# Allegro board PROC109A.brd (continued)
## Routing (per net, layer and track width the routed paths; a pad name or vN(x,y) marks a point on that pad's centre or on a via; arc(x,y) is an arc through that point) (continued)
PRG1_CPSW_RGMII1_TD0: length 31.3
  TOP w0.135: v1(132.51,-42.34) 133.2,-42.34 135.25,-44.39 U19.28
  L03_SIG1 w0.121: v1(111.87,-42.26) 112.31,-42.26 112.6,-42.55 126.18,-42.55 126.3,-42.67 126.3,-42.93 126.42,-43.05 126.66,-43.05 126.78,-42.93 126.78,-42.67 126.9,-42.55 127.15,-42.55 127.27,-42.67 127.27,-42.93 127.39,-43.05 127.63,-43.05 127.75,-42.93 127.75,-42.67 127.87,-42.55 128.11,-42.55 128.23,-42.67 128.23,-42.93 128.35,-43.05 128.59,-43.05 128.71,-42.93 128.71,-42.67 128.83,-42.55 130.41,-42.55 131.34,-43.48 132.01,-43.48 132.51,-42.98 v1(132.51,-42.34)
  BOTTOM w0.135: U40.2 111.44,-41.84 v1(111.87,-42.26)
PRG1_CPSW_RGMII1_TD1: length 31.2
  TOP w0.135: U19.27 135.26,-43.89 134.16,-42.8 v1(134.16,-41.73)
  L03_SIG1 w0.121: v1(134.16,-41.73) 134.7,-41.73 134.86,-41.9 134.86,-42.07 134.44,-42.49 133.53,-42.49 132.29,-43.73 125.75,-43.73 125.47,-43.45 113.86,-43.45 113.26,-42.85 111.28,-42.85 v1(110.77,-42.34)
  BOTTOM w0.135: v1(110.77,-42.34) 110.77,-42.34 U40.3
PRG1_CPSW_RGMII1_TD2: length 31.2
  TOP w0.135: v1(134.92,-42.88) 135.44,-43.39 U19.26
  L03_SIG1 w0.121: v1(111.87,-43.29) 113.16,-43.29 113.7,-43.82 120.23,-43.82 120.75,-44.34 126.06,-44.34 126.18,-44.46 126.18,-44.81 126.3,-44.93 126.54,-44.93 126.66,-44.81 126.66,-44.39 126.78,-44.27 127.02,-44.27 127.14,-44.39 127.14,-44.81 127.26,-44.93 127.51,-44.93 127.63,-44.81 127.63,-44.39 127.75,-44.27 127.99,-44.27 128.11,-44.39 128.11,-44.81 128.23,-44.93 128.47,-44.93 128.59,-44.81 128.59,-44.46 128.71,-44.34 132.08,-44.34 133.55,-42.88 v1(134.92,-42.88)
  BOTTOM w0.135: U40.4 111.42,-42.84 v1(111.87,-43.29)
PRG1_CPSW_RGMII1_TD3: length 31.2
  TOP w0.135: U19.25 135.88,-42.89 135.69,-42.7 v1(135.69,-41.73)
  L03_SIG1 w0.121: v1(110.68,-43.34) 111.05,-43.71 112.37,-43.71 113.57,-44.91 120.3,-44.91 120.59,-45.2 131.84,-45.2 133.4,-43.64 135.33,-43.64 136,-42.97 136,-42.04 v1(135.69,-41.73)
  BOTTOM w0.135: U40.5 v1(110.68,-43.34)
PRG1_CPSW_RGMII1_TX_CTL: length 30.5
  TOP w0.135: U19.37 136.66,-49.14 136.58,-49.23 v1(136.12,-49.23)
  L03_SIG1 w0.121: v1(111.87,-44.2) 111.87,-44.96 112.85,-45.95 114.71,-45.95 115.32,-46.56 133.89,-46.56 136.12,-48.78 v1(136.12,-49.23)
  BOTTOM w0.135: v1(111.87,-44.2) 111.5,-43.84 U40.6
PRG1_CPSW_RGMII1_TXC: length 31.3
  TOP w0.135: U19.29 135.19,-44.89 133.35,-43.05 v1(131.76,-43.05)
  L03_SIG1 w0.121: v1(110.68,-44.34) 110.24,-43.9 110.24,-42.17 110.57,-41.84 121.05,-41.84 121.54,-41.35 127.71,-41.35 128.27,-41.91 130.61,-41.91 v1(131.76,-43.05)
  BOTTOM w0.135: U40.7 v1(110.68,-44.34)
PRG1_CPSW_RGMII2_CLK: length 19.5
  TOP w0.135: R50.2 130.58,-27.94 132.18,-26.34 132.18,-20.02 133.35,-18.85 138.28,-18.85 138.79,-19.36 R13.1
PRG1_CPSW_RGMII2_CLK_R: length 2.7
  TOP w0.135: R50.1 126.29,-27.94 126.03,-27.69 126.03,-27.38 125.79,-27.14 U6.5
PRG1_CPSW_RGMII2_GPIO_1: length 43.9
  TOP w0.135: U7.22 138.18,-21.62 v1(137.72,-21.16) 137.71,-21.17 R12.2
  L03_SIG1 w0.121: v1(162.18,-21.41) 162.18,-20.37 160.35,-18.54 139.83,-18.54 137.72,-20.65 v1(137.72,-21.16)
  BOTTOM w0.135: R12.2 137.71,-21.17 v1(137.72,-21.16) ; Q12.3 162.94,-30.47 162.18,-29.72 v1(162.18,-21.41)
PRG1_CPSW_RGMII2_RD0: length 73.8
  TOP w0.102: 87.62,-44.31 U18.AA10
  TOP w0.135: v1(133.99,-28.78) 133.83,-28.93 133.83,-29.38 R64.1 134.52,-29.51 134.7,-29.34 134.7,-28.65 135.5,-27.84 U7.33 ; v1(104.78,-39.5) 103.99,-39.5 103.33,-40.16 103.33,-41.07 102.74,-41.66 101.98,-41.66 98.73,-44.91 89,-44.91 88.41,-44.31 87.62,-44.31
  L03_SIG1 w0.121: v1(133.99,-28.78) 133.4,-29.36 132.72,-29.36 132.23,-28.88 131.62,-28.88 131.45,-28.71 131.45,-26.8 131.33,-26.68 130.99,-26.68 130.87,-26.8 130.87,-29 130.74,-29.12 130.44,-29.12 130.28,-28.96 130.28,-26.95 130.13,-26.8 129.79,-26.8 127.93,-28.66 121.96,-28.66 121.87,-28.75 121.31,-28.75 121.22,-28.66 120.86,-28.66 117.26,-32.25 117.26,-32.54 116.87,-32.94 116.58,-32.94 115.4,-34.11 115.4,-34.12 114.63,-34.89 114.63,-36.94 113.27,-38.3 102.74,-38.3 102.62,-38.42 102.62,-39.38 102.74,-39.5 v1(104.78,-39.5)
  BOTTOM w0.135: v1(133.99,-28.78) 133.99,-29.48 R64.1
PRG1_CPSW_RGMII2_RD1: length 73.6
  TOP w0.102: 87.74,-44.59 86.67,-44.59 U18.Y10
  TOP w0.135: 87.74,-44.59 88.28,-44.59 88.87,-45.18 98.96,-45.18 102.18,-41.96 102.82,-41.96 103.76,-41.02 v1(103.76,-40.51) ; v1(133.99,-30.24) 133.99,-30.25 133.78,-30.45 133.78,-30.75 R68.2 134.51,-30.94 135,-30.45 135,-28.98 135.64,-28.34 U7.34
  L03_SIG1 w0.121: v1(133.99,-30.24) 127.44,-30.24 127.1,-30.58 126.45,-30.58 126.13,-30.26 126.13,-29.29 126.01,-29.17 125.77,-29.17 125.65,-29.29 125.65,-30.26 125.53,-30.38 125.29,-30.38 125.17,-30.26 125.17,-29.29 125.05,-29.17 124.81,-29.17 124.69,-29.29 124.69,-30.98 124.57,-31.1 124.32,-31.1 124.2,-30.98 124.2,-29.29 124.08,-29.17 123.84,-29.17 123.72,-29.29 123.72,-30.26 123.6,-30.38 122.4,-30.38 119.38,-33.4 119.38,-34.82 118.44,-35.76 116.53,-35.76 113.48,-38.81 107.11,-38.81 104.14,-41.78 102.36,-41.78 102.23,-41.66 102.23,-41.17 102.36,-41.05 103.23,-41.05 v1(103.76,-40.51)
  BOTTOM w0.135: v1(133.99,-30.24) 133.99,-30.92 R68.2
PRG1_CPSW_RGMII2_RD2: length 73.7
  TOP w0.102: 87.33,-43.54 86.67,-43.54 U18.Y11
  TOP w0.135: v1(132.49,-32.08) 132.63,-32.23 R71.1 133.24,-32.23 133.82,-31.65 134.29,-31.65 135.28,-30.66 135.28,-29.16 135.6,-28.84 U7.35 ; 87.33,-43.54 87.37,-43.58 95.86,-43.58 97.93,-41.52 100.04,-41.52 v1(100.63,-42.11)
  L03_SIG1 w0.121: v1(100.63,-42.11) 101.57,-43.05 104.27,-43.05 104.52,-42.8 104.52,-41.78 107.24,-39.07 113.59,-39.07 116.64,-36.02 118.54,-36.02 119.63,-34.92 119.63,-33.51 121.6,-31.55 123.91,-31.55 124.59,-32.23 127.6,-32.23 127.72,-32.11 127.72,-30.65 127.84,-30.53 128.08,-30.53 128.2,-30.65 128.2,-32.14 128.32,-32.26 128.56,-32.26 128.68,-32.14 128.68,-30.65 128.8,-30.53 129.04,-30.53 129.16,-30.65 129.16,-32.14 129.28,-32.26 129.53,-32.26 129.65,-32.14 129.65,-30.65 129.77,-30.53 130.01,-30.53 130.13,-30.65 130.13,-32.14 130.25,-32.26 130.49,-32.26 130.61,-32.14 130.61,-30.65 130.73,-30.53 130.97,-30.53 131.09,-30.65 131.09,-31.86 131.32,-32.08 v1(132.49,-32.08)
  BOTTOM w0.135: v1(132.49,-32.08) 132.71,-32.3 R230.2
PRG1_CPSW_RGMII2_RD3: length 73.6
  TOP w0.102: v2(85.36,-43.77) 85.39,-43.74 U18.V12
  TOP w0.135: U7.36 135.74,-29.34 135.59,-29.5 135.59,-30.82 134.73,-31.68 R72.1 134.94,-32.44 135.28,-32.44 v1(135.48,-32.23)
  L03_SIG1 w0.102: v2(85.36,-43.77) 85.42,-43.71 86.19,-43.71 86.31,-43.59 87.6,-43.59
  L03_SIG1 w0.121: 87.6,-43.59 88.22,-42.98 98.15,-42.98 100.28,-45.11 101.8,-45.11 102.58,-44.34 105.52,-44.34 106.25,-43.61 106.25,-42.56 108.97,-39.83 117.87,-39.83 118.59,-39.11 118.59,-36.4 119.48,-35.51 119.99,-35.51 122.78,-32.72 126.35,-32.72 126.47,-32.84 126.47,-33.18 126.59,-33.3 126.83,-33.3 126.95,-33.18 126.95,-32.84 127.07,-32.72 127.32,-32.72 127.44,-32.84 127.44,-33.18 127.56,-33.3 127.8,-33.3 127.92,-33.18 127.92,-32.84 128.04,-32.72 128.28,-32.72 128.4,-32.84 128.4,-33.18 128.52,-33.3 128.76,-33.3 128.88,-33.18 128.88,-32.84 129.01,-32.72 129.25,-32.72 129.37,-32.84 129.37,-33.18 129.49,-33.3 129.73,-33.3 129.85,-33.18 129.85,-32.84 129.97,-32.72 133.06,-32.72 133.19,-32.59 133.19,-31.34 133.31,-31.22 133.53,-31.22 133.67,-31.36 133.67,-32.42 133.79,-32.54 134.03,-32.54 134.15,-32.42 134.15,-31.34 134.28,-31.22 134.52,-31.22 134.64,-31.34 134.64,-32.59 134.76,-32.71 135.01,-32.71 v1(135.48,-32.23)
  BOTTOM w0.135: R229.2 134.79,-32.23 v1(135.48,-32.23)
PRG1_CPSW_RGMII2_RSTN: length 5.1
  TOP w0.135: U7.43 140.18,-32.16 v1(139.06,-33.27)
  BOTTOM w0.135: U34.4 138.45,-33.39 138.57,-33.27 v1(139.06,-33.27)
PRG1_CPSW_RGMII2_RX_CTL: length 73.8
  TOP w0.102: 87.49,-43.32 U18.Y12
  TOP w0.135: 87.49,-43.32 95.62,-43.32 97.69,-41.25 99.97,-41.25 v1(100.2,-41.02) ; U7.38 137.68,-31.07 137.41,-31.35 136.56,-31.35 136.22,-31.69 R73.2 136.44,-32.44 136.73,-32.44 v1(136.93,-32.23)
  L03_SIG1 w0.121: v1(100.2,-41.02) 101.22,-40 105.33,-40 106.78,-38.56 113.38,-38.56 116.5,-35.43 118.4,-35.43 118.6,-35.24 118.6,-33.16 119.27,-32.5 119.73,-32.5 119.9,-32.33 119.9,-32.16 119.08,-31.34 119.08,-31.17 119.25,-30.99 119.42,-30.99 120.24,-31.81 120.43,-31.81 120.59,-31.66 120.59,-31.49 119.76,-30.65 119.76,-30.48 119.93,-30.31 120.1,-30.31 120.94,-31.16 121.14,-31.16 121.3,-31 121.3,-30.83 120.44,-29.97 120.44,-29.8 120.61,-29.63 120.78,-29.63 121.63,-30.48 121.85,-30.48 121.99,-30.33 121.99,-30.16 121.12,-29.29 121.12,-29.12 121.24,-29 121.98,-29 122.06,-28.91 126.7,-28.91 127.7,-29.91 132.9,-29.91 133.17,-29.64 134.34,-29.64 v1(136.93,-32.23)
  BOTTOM w0.135: v1(136.93,-32.23) 136.86,-32.3 R228.1
PRG1_CPSW_RGMII2_RXC: length 70.4
  TOP w0.102: U18.V10 84.98,-44.31 v2(84.93,-44.37)
  TOP w0.135: v1(132.18,-28.07) 132.95,-28.07 R51.1
  L03_SIG1 w0.121: v1(132.18,-28.07) 134.19,-28.07 136.35,-30.23 136.35,-30.89 137.54,-32.08 137.54,-33.31 136.34,-34.51 131.34,-34.51 130.84,-34.01 125.29,-34.01 123.74,-35.56 121.92,-35.56 120.98,-36.5 120.98,-38.13 118.76,-40.34 110.93,-40.34 104.56,-46.71 103.48,-46.71 102.85,-46.08 96.8,-46.08 95.63,-44.9 87.6,-44.9 87.35,-44.65 85.21,-44.65 v2(84.93,-44.37)
PRG1_CPSW_RGMII2_RXC_R: length 2.8
  TOP w0.135: R51.2 134.5,-28.05 135.21,-27.34 U7.32
PRG1_CPSW_RGMII2_TD0: length 75.4
  TOP w0.102: U18.Y6 87.39,-46.31 87.74,-46.66
  TOP w0.135: U7.28 135.06,-25.34 134.66,-24.95 v1(134.66,-24.51) ; v1(112.52,-37.34) 113,-37.34 113.79,-38.13 113.79,-38.9 113.66,-39.04 113.16,-39.04 113.03,-39.17 113.03,-39.44 113.16,-39.58 114.11,-39.58 114.25,-39.71 114.25,-39.98 114.11,-40.12 113.16,-40.12 113.03,-40.25 113.03,-40.52 113.16,-40.66 114.11,-40.66 114.25,-40.79 114.25,-44.78 113.06,-45.97 110.29,-45.97 109.52,-46.74 109.52,-47.42 108.98,-47.97 96.89,-47.97 96.24,-48.62 89.69,-48.62 87.74,-46.66
  L03_SIG1 w0.121: v1(112.52,-37.34) 112.52,-35.79 115.46,-32.85 115.46,-32.25 120.63,-27.09 120.63,-25.71 121.97,-24.36 128,-24.36 128.61,-23.75 133.9,-23.75 v1(134.66,-24.51)
PRG1_CPSW_RGMII2_TD1: length 75.4
  TOP w0.102: 87.74,-45.52 87.73,-45.51 87.09,-45.51 U18.AA8
  TOP w0.135: 87.74,-45.52 89.15,-46.94 96.16,-46.94 96.9,-46.2 100.74,-46.2 102.3,-44.64 102.84,-44.64 104.78,-42.7 104.78,-41.83 105.08,-41.53 107.11,-41.53 v1(111.3,-37.34) ; U7.27 135.56,-24.84 135.56,-24.84 v1(135.52,-24.84)
  L03_SIG1 w0.121: v1(135.52,-24.84) 136.42,-24.84 136.63,-25.04 136.63,-25.42 136.51,-25.54 134.53,-25.54 134.41,-25.66 134.41,-25.9 134.53,-26.02 135.24,-26.02 135.36,-26.14 135.36,-26.42 135.49,-26.54 135.73,-26.54 135.85,-26.42 135.85,-26.14 135.97,-26.02 136.51,-26.02 136.63,-26.14 136.63,-27.31 136.48,-27.46 133.63,-27.46 133.27,-27.09 133.27,-24.5 132.79,-24.03 128.88,-24.03 128.27,-24.64 122.17,-24.64 120.95,-25.86 120.95,-27.12 115.72,-32.35 115.72,-32.96 113.94,-34.73 113.94,-36.78 112.93,-37.79 111.76,-37.79 v1(111.3,-37.34)
PRG1_CPSW_RGMII2_TD2: length 75.4
  TOP w0.102: U18.Y9 87.31,-44.81
  TOP w0.135: v1(134.6,-23.18) 134.6,-23.63 135.32,-24.34 U7.26 ; v1(108.25,-37.34) 105.59,-40 105.28,-40 103.12,-42.16 103.12,-42.67 102.49,-43.31 101.22,-43.31 99.08,-45.45 88.66,-45.45 88.14,-44.93 87.43,-44.93 87.31,-44.81
  L03_SIG1 w0.121: v1(108.25,-37.34) 107.81,-37.34 107.77,-37.3 101.74,-37.3 101.52,-37.08 101.52,-36.74 101.73,-36.54 111.42,-36.54 115.21,-32.75 115.21,-32.14 120.37,-26.98 120.37,-25.6 121.87,-24.11 127.89,-24.11 128.51,-23.49 134.29,-23.49 v1(134.6,-23.18)
PRG1_CPSW_RGMII2_TD3: length 74.9
  TOP w0.102: U18.W9 85.89,-45.24 v2(85.93,-45.28)
  TOP w0.135: U7.25 135.74,-23.84 135.52,-23.62 v1(135.52,-23.18)
  L03_SIG1 w0.121: v2(85.93,-45.28) 87.04,-45.28 87.17,-45.42 95.05,-45.42 96.22,-46.59 102.62,-46.59 103.3,-47.27 106.54,-47.27 109.65,-44.16 109.65,-42.39 110.46,-41.58 119.93,-41.58 123.48,-38.04 123.48,-36.54 125.5,-34.52 130.56,-34.52 131.06,-35.02 136.56,-35.02 138.84,-32.74 138.84,-28.75 137.29,-27.2 137.29,-24.95 v1(135.52,-23.18)
PRG1_CPSW_RGMII2_TX_CTL: length 74.8
  TOP w0.102: v2(85.36,-45.28) 85.39,-45.24 U18.V9
  TOP w0.135: U7.37 137.18,-30.83 137.19,-30.84 v1(137.19,-30.89)
  L03_SIG1 w0.121: v1(137.19,-30.89) 137.19,-30.45 135.01,-28.28 135.01,-28.01 135.25,-27.76 137.48,-27.76 138.58,-28.86 138.58,-32.64 136.45,-34.77 131.16,-34.77 130.66,-34.27 125.39,-34.27 123.72,-35.94 123.1,-35.94 122.28,-36.76 122.28,-37.96 119.47,-40.77 113.42,-40.77 112.86,-41.33 110.36,-41.33 109.4,-42.29 109.4,-43.22 105.65,-46.96 103.37,-46.96 102.74,-46.34 96.47,-46.34 95.3,-45.16 87.43,-45.16 87.18,-44.92 85.73,-44.92 v2(85.36,-45.28)
PRG1_CPSW_RGMII2_TXC: length 8
  TOP w0.102: 87.74,-45.24 87.35,-45.24 87.15,-45.04 86.67,-45.04 U18.Y8
  TOP w0.135: 87.74,-45.24 88.01,-45.24 88.59,-45.82 93.25,-45.82 93.72,-46.29 R23.1
PRG1_CPSW_RGMII2_TXC_R: length 67.1
  TOP w0.135: R23.2 96.09,-46.33 96.62,-45.8 99.62,-45.8 101.6,-43.81 103.15,-43.81 104.47,-42.49 104.47,-41.71 105.13,-41.05 106.07,-41.05 v1(109.78,-37.34) ; U7.29 135.14,-25.84 134.09,-24.79 v1(132.61,-24.79)
  L03_SIG1 w0.121: v1(109.78,-37.34) 110.49,-38.05 113.08,-38.05 114.27,-36.86 114.27,-34.76 116.36,-32.68 116.76,-32.68 117.01,-32.43 117.01,-32.09 120.88,-28.22 123.46,-28.22 123.58,-28.1 123.58,-26.54 123.73,-26.39 123.92,-26.39 124.06,-26.54 124.06,-28.1 124.18,-28.22 124.4,-28.22 124.52,-28.1 124.52,-26.51 124.64,-26.39 124.88,-26.39 125,-26.51 125,-28.07 125.15,-28.22 125.36,-28.22 125.48,-28.1 125.48,-26.51 125.6,-26.39 125.85,-26.39 125.97,-26.51 125.97,-28.07 126.11,-28.22 126.33,-28.22 126.45,-28.1 126.45,-26.51 126.57,-26.39 126.84,-26.39 126.96,-26.51 126.96,-28.1 127.15,-28.3 127.56,-28.3 131.06,-24.79 v1(132.61,-24.79)
PRG1_CPSW_RGMII_INTN: length 94.1
  TOP w0.102: 87.74,-42.68 87.62,-42.68 87.62,-42.68 87.03,-42.68 U18.AA13
  TOP w0.135: v1(142.39,-51.28) 142.21,-51.46 141.85,-51.46 R136.2 141.66,-50.8 140.68,-49.82 U19.44 ; U7.44 140.68,-31.67 v1(140.69,-31.67) ; 87.74,-42.68 94.93,-42.68 94.94,-42.67 95,-42.67 97.04,-40.62 99.33,-40.62 99.63,-40.32 101.36,-40.32 101.98,-40.94 102.41,-40.94 102.67,-40.69 102.67,-39.79 103.69,-38.77 105.75,-38.77 107.97,-36.56 108.57,-36.56 108.79,-36.34 114.62,-36.34 115.7,-37.41 123.12,-37.41 v1(124.44,-38.73)
  L03_SIG1 w0.121: v1(140.69,-31.67) 140.69,-32.33 137.64,-35.38 131.04,-35.38 130.43,-34.78 125.62,-34.78 123.73,-36.67 123.73,-38.03 v1(124.44,-38.73)
  BOTTOM w0.135: v1(142.39,-51.28) 142.39,-50.83 141.66,-50.11 141.14,-50.11 136.69,-45.66 136.69,-42.21 136.69,-42.15 136.69,-36.18 137.85,-35.03 138.87,-35.03 139.5,-34.4 139.5,-33.33 140.69,-32.13 v1(140.69,-31.67)
PRG1_IEP0_EDC_LATCH_IN0: length 33
  TOP w0.102: U18.Y4 86.67,-47.59 87.14,-47.59 87.58,-48.03 87.58,-48.03 87.74,-48.19
  TOP w0.135: 87.74,-48.19 89.42,-49.88 89.46,-49.91 98.15,-49.91 v1(98.73,-50.5)
  BOTTOM w0.135: v1(98.73,-50.5) 98.78,-50.54 98.78,-55.39 98.91,-55.52 108.72,-55.52 J5.8
PRG1_IEP0_EDC_LATCH_IN1: length 53.4
  TOP w0.102: U18.V13 85.41,-42.82 v2(85.93,-42.3)
  L03_SIG1 w0.102: v2(85.93,-42.3) 86.65,-42.3 87.44,-41.5 87.74,-41.5
  L03_SIG1 w0.121: 87.74,-41.5 98.72,-41.5 100.65,-43.43 104.39,-43.43 105.35,-42.48 105.38,-42.48 105.63,-42.23 105.63,-42.2 108.51,-39.32 114.45,-39.32 v1(114.88,-38.89)
  BOTTOM w0.135: v1(114.88,-38.89) 114.88,-53.97 116.95,-56.04 J5.12
PRG1_IEP0_EDC_SYNC_OUT0: length 34.1
  TOP w0.102: v2(85.36,-47.86) 85.31,-47.81 U18.U3
  L03_SIG1 w0.121: v1(98.73,-49) 88.32,-49 87.71,-48.39 85.89,-48.39 v2(85.36,-47.86)
  BOTTOM w0.135: v1(98.73,-49) 98.73,-49.89 98.3,-50.32 98.3,-50.67 98.51,-50.88 98.51,-55.51 98.81,-55.8 108,-55.8 109.33,-57.13 J5.6
PRG1_IEP0_EDC_SYNC_OUT1: length 36.1
  TOP w0.102: 84.41,-49.66 84.41,-49.33 84.11,-49.04 84.11,-48.59 U18.T2
  TOP w0.135: 84.41,-49.66 84.41,-49.87 86.44,-51.89 86.44,-52.99 88.3,-54.85 98.62,-54.85 98.69,-54.91 v1(99.21,-54.91)
  BOTTOM w0.135: v1(99.21,-54.91) 110.65,-54.91 J5.10
PRG1_MDIO0_MDC: length 103.3
  TOP w0.102: U18.W1 86.23,-49.15
  TOP w0.135: v1(91.92,-51.33) 91.39,-50.8 87.88,-50.8 86.23,-49.15 ; v1(139.67,-30.91) 139.68,-30.9 U7.42 ; U19.42 v1(139.68,-50.05)
  L03_SIG1 w0.121: v1(139.68,-50.05) 142.04,-47.7 142.04,-43.64 141.4,-43 138.18,-43 137.69,-43.48 137.69,-48.51 138.96,-49.78 138.96,-50.52 138.69,-50.79 138.69,-53.59 137.72,-54.56 133.08,-54.56 131.89,-53.37 124.77,-53.37 124.67,-53.47 116.11,-53.47 115.6,-52.96 99.53,-52.96 97.48,-50.91 92.35,-50.91 v1(91.92,-51.33)
  BOTTOM w0.135: v1(139.67,-30.91) 139.99,-31.23 139.99,-32.3 139.52,-32.77 138.66,-32.77 136.42,-35 136.42,-41.31 136.42,-41.38 136.42,-46.79 v1(139.68,-50.05)
PRG1_MDIO0_MDIO: length 88.9
  TOP w0.102: 85.41,-49.24 85.39,-49.22 U18.V2
  TOP w0.114: 85.83,-49.66 85.41,-49.24
  TOP w0.135: 85.83,-49.66 87.99,-51.82 v1(89.74,-51.82) ; U7.41 139.18,-31.34 139.42,-31.58 v1(139.42,-32.03) ; U19.41 139.18,-50 139.25,-50.07 139.25,-50.64 139.42,-50.81 v1(139.42,-51.26) 139.44,-51.28 R135.2
  L03_SIG1 w0.121: v1(139.42,-51.26) 139.42,-53.82 138.07,-55.17 132.74,-55.17 131.82,-54.25 125.5,-54.25 124.63,-55.12 116.94,-55.12 115.29,-53.47 99.31,-53.47 97.85,-52 92.42,-52 91.87,-52.55 90.47,-52.55 v1(89.74,-51.82)
  BOTTOM w0.135: v1(139.42,-51.26) 139.42,-50.55 136.16,-47.29 136.15,-47.28 136.15,-47.26 136.15,-41.34 136.15,-41.29 136.15,-34.91 136.15,-34.89 136.16,-34.88 139.01,-32.03 v1(139.42,-32.03)
PRG1_RGMII1_RD0: length 25.9
  TOP w0.102: U18.V4 85.93,-47.85 85.93,-47.86 v2(85.93,-47.86)
  L03_SIG1 w0.121: v1(100.63,-48.67) 101.08,-48.67 101.19,-48.78 101.19,-49.13 101.07,-49.25 99.8,-49.25 99.11,-48.56 88.52,-48.56 87.81,-47.86 v2(85.93,-47.86)
  BOTTOM w0.135: v1(100.63,-48.67) 100.63,-49.27 100.85,-49.48 101.47,-49.48 101.68,-49.27 101.68,-48.62 104.45,-45.84 U40.29
PRG1_RGMII1_RD1: length 25.9
  TOP w0.102: U18.W5 85.89,-47.26 v2(85.93,-47.29)
  L03_SIG1 w0.121: v2(85.93,-47.29) 87.82,-47.29 88.77,-48.21 88.92,-48.21 88.95,-48.24 101.18,-48.24 101.96,-49.02 101.96,-49.4 102.92,-50.37 103.25,-50.37 103.56,-50.06 103.56,-49.78 v1(102.59,-48.82)
  BOTTOM w0.135: U40.27 104.57,-46.84 v1(102.59,-48.82)
PRG1_RGMII1_RD2: length 25.9
  TOP w0.102: 87.74,-47.81 87.24,-47.31 U18.AA4
  TOP w0.135: v1(102.26,-50.47) 102.7,-50.91 103.62,-50.91 103.89,-50.65 103.89,-49.83 103.66,-49.61 89.54,-49.61 87.74,-47.81
  BOTTOM w0.135: v1(102.26,-50.47) 104.89,-47.84 U40.25
PRG1_RGMII1_RD3: length 25.9
  TOP w0.102: 87.56,-46.87 87.23,-46.54 86.67,-46.54 U18.Y5
  TOP w0.135: 87.56,-46.87 89.64,-48.95 96.52,-48.95 97.23,-48.24 106.27,-48.24 106.4,-48.37 106.4,-49.78 106.27,-49.91 105.54,-49.91 105.32,-49.69 v1(105.32,-48.84)
  BOTTOM w0.135: U40.23 v1(105.32,-48.84)
PRG1_RGMII1_RX_CTL: length 25.9
  TOP w0.102: U18.AA5 87.13,-46.81 87.74,-47.43
  TOP w0.135: v1(105.21,-50.5) 104.04,-49.33 100.23,-49.33 99.47,-48.57 97.66,-48.57 96.95,-49.28 89.59,-49.28 87.74,-47.43
  BOTTOM w0.135: v1(105.21,-50.5) 104.76,-50.5 104.65,-50.61 104.65,-51.55 104.78,-51.69 106.17,-51.69 107.25,-50.61 U40.21
PRG1_RGMII1_RXC: length 26
  TOP w0.102: U18.Y2 86.67,-48.04 87.01,-48.04 87.17,-48.2 87.17,-48.51 87.74,-49.08
  TOP w0.135: v1(103.68,-52.4) 102.97,-51.69 97.66,-51.69 96.49,-50.52 89.18,-50.52 87.74,-49.08
  BOTTOM w0.135: U40.19 108.25,-50.7 106.07,-52.88 104.17,-52.88 v1(103.68,-52.4)
PRG1_RGMII1_TD0: length 37.9
  TOP w0.102: v2(84.93,-46.77) 84.98,-46.81 U18.V5
  L03_SIG1 w0.121: v1(98.76,-47.31) 98.57,-47.13 88.76,-47.13 88.14,-46.51 85.19,-46.51 v2(84.93,-46.77)
  BOTTOM w0.135: U40.41 108.25,-40.2 106.35,-38.3 105.99,-38.3 104.9,-37.21 102.72,-37.21 99.49,-40.44 99.49,-42.14 98.44,-43.19 98.44,-43.97 98.57,-44.1 99.38,-44.1 99.52,-44.24 99.52,-44.51 99.38,-44.64 98.57,-44.64 98.44,-44.77 98.44,-45.04 98.57,-45.18 99.38,-45.18 99.52,-45.31 99.52,-45.58 99.38,-45.72 98.57,-45.72 98.44,-45.85 98.44,-46.99 v1(98.76,-47.31)
PRG1_RGMII1_TD1: length 37.7
  TOP w0.102: U18.W2 85.61,-48.59 85.61,-49.06 86.21,-49.66
  TOP w0.135: v1(100.56,-52.37) 100.24,-52.06 91.73,-52.06 90.75,-51.08 87.63,-51.08 86.64,-50.09 86.64,-50.09 86.21,-49.66
  BOTTOM w0.135: U40.39 107.25,-40.39 107.24,-40.39 105.92,-39.07 102.06,-39.07 101.13,-39.99 101.13,-40.99 100.1,-42.01 100.1,-51.92 v1(100.56,-52.37)
PRG1_RGMII1_TD2: length 37.6
  TOP w0.102: U18.V6 85.39,-45.89 v2(85.36,-45.86)
  L03_SIG1 w0.121: v2(85.36,-45.86) 85.73,-46.23 88.34,-46.23 88.98,-46.87 100.24,-46.87 v1(100.63,-47.27)
  BOTTOM w0.135: v1(100.63,-47.27) 101.22,-47.27 101.38,-47.11 101.38,-46.7 101.17,-46.48 100.61,-46.48 100.47,-46.35 100.47,-46.08 100.61,-45.94 101.21,-45.94 101.35,-45.81 101.35,-45.54 101.21,-45.41 100.61,-45.41 100.47,-45.27 100.47,-45 100.61,-44.87 101.06,-44.87 101.19,-44.73 101.19,-44.46 101.06,-44.33 100.61,-44.33 100.47,-44.19 100.47,-43.93 100.61,-43.79 101.21,-43.79 101.35,-43.66 101.35,-43.39 101.21,-43.25 100.61,-43.25 100.47,-43.12 100.47,-42.85 100.61,-42.71 101.21,-42.71 101.4,-42.53 101.4,-40.13 101.9,-39.62 104.27,-39.62 104.73,-40.09 104.92,-40.09 105.5,-39.52 105.77,-39.52 105.94,-39.69 105.94,-39.96 105.18,-40.72 105.18,-40.91 105.61,-41.34 U40.38
PRG1_RGMII1_TD3: length 37.7
  TOP w0.102: U18.AA7 87.65,-45.81 87.74,-45.9
  TOP w0.135: v1(105.21,-42.06) 106.16,-42.06 106.73,-42.62 109.73,-42.62 110.08,-42.98 110.08,-45.03 109.73,-45.39 107.14,-45.39 106.83,-45.08 106.83,-43.38 106.17,-42.72 105.23,-42.72 103.3,-44.65 103.3,-45.21 102.04,-46.47 97.22,-46.47 95.68,-48.01 89.84,-48.01 87.74,-45.9
  BOTTOM w0.135: v1(105.21,-42.06) 105.21,-42.32 105.36,-42.47 105.61,-42.47 105.74,-42.34 U40.36
PRG1_RGMII1_TX_CTL: length 37.6
  TOP w0.102: U18.Y7 86.69,-46.11 87.57,-46.11 87.74,-46.28
  TOP w0.135: 87.74,-46.28 89.79,-48.34 95.96,-48.34 97.54,-46.76 102.41,-46.76 103.26,-47.61 106.37,-47.61 106.56,-47.41 106.56,-47.05 106.43,-46.91 104.71,-46.91 104.52,-46.73 104.52,-46.48 104.66,-46.35 106.43,-46.35 106.56,-46.22 106.56,-45.97 106.4,-45.81 104.73,-45.81 104.6,-45.68 104.6,-45.43 104.73,-45.3 106.43,-45.3 106.56,-45.16 106.56,-44.89 106.43,-44.76 105.39,-44.76 105.26,-44.63 105.26,-44.36 105.39,-44.22 106.16,-44.22 106.3,-44.09 106.3,-43.47 106.16,-43.34 v1(105.32,-43.34)
  BOTTOM w0.135: U40.34 v1(105.32,-43.34)
PRG1_RGMII1_TXC: length 30.7
  L03_SIG1 w0.121: v1(102.11,-47.35) 102.95,-47.35 103.34,-47.74 103.34,-47.91 103.2,-48.06 102.03,-48.06 101.71,-47.73 93,-47.73 92.82,-47.55 v1(92.38,-47.55)
  BOTTOM w0.135: U40.32 105.05,-44.34 104.9,-44.2 102.74,-44.2 101.79,-45.15 101.79,-45.72 101.93,-45.85 102.91,-45.85 103.05,-45.99 103.05,-46.32 102.91,-46.46 101.93,-46.46 101.79,-46.59 101.79,-47.03 v1(102.11,-47.35) ; R286.2 90.06,-50.18 90.35,-50.47 92.41,-50.47 93.17,-49.71 93.17,-48.34 v1(92.38,-47.55)
PRG_CPSW_RGMII1_MUX_SEL: length 49.5
  TOP w0.102: U18.Y20 86.11,-39.04 86.11,-38.7 86.37,-38.44 86.73,-38.44 87.2,-37.97
  TOP w0.135: R62.1 97.34,-30.81 v1(97.33,-30.81) 96.76,-30.81 94.2,-33.38 91.8,-33.38 87.2,-37.97
  L03_SIG1 w0.121: v1(110.36,-33.11) 109.97,-33.51 107.93,-33.51 105.15,-30.73 97.41,-30.73 v1(97.33,-30.81)
  BOTTOM w0.135: v1(110.36,-33.11) 110.36,-37.21 113.47,-40.31 113.47,-44.85 112.95,-45.36 112.24,-45.36 112.03,-45.57 R250.2 111.43,-45.97 111.05,-45.59 110.74,-45.59 ; U40.9 110.49,-45.34 110.74,-45.59 ; U40.10 110.49,-45.84 110.74,-45.59 110.74,-45.59
QSPI_RST_N: length 3.7
  TOP w0.135: v1(78.49,-25.43) 78.51,-25.4 U2.3
  BOTTOM w0.135: U31.4 77.64,-25.43 v1(78.49,-25.43)
R_BP_CONN_1_PORZ: length 3
  TOP w0.135: R4.1 R8.2 27.78,-17.55 27.94,-17.39 U1.3
R_BP_CONN_2_PORZ: length 3.2
  TOP w0.135: R2.2 R3.1 U1.6
SENCE3_IP: length 4
  BOTTOM w0.135: R188.2 21.37,-21.73 20.24,-20.6 U27.8
SOC_ADC0_AIN0: length 62.4
  TOP w0.102: 80.39,-37.97 U18.H21
  TOP w0.135: R142.1 R143.2 43.65,-53.89 45.17,-52.37 51.59,-52.37 v1(52.78,-51.18) ; 80.39,-37.97 80.39,-36.17 79.96,-35.74 79.96,-31.62 78.11,-29.77 72.39,-29.77 71.56,-30.6 67.73,-30.6 67.21,-31.11 64.41,-31.11 63.63,-31.9 v1(63.63,-32.92) 63.63,-33.57 C28.1
  BOTTOM w0.135: v1(52.78,-51.18) 55.41,-48.55 55.41,-39.69 62.18,-32.92 v1(63.63,-32.92)
SOC_ADC0_AIN1: length 48.1
  TOP w0.102: v2(79.83,-39.78) 79.79,-39.82 U18.F19
  TOP w0.135: v1(58.72,-51.28) 57.84,-52.17 57.84,-53.42 57.37,-53.89 R153.1 R152.2
  L03_SIG1 w0.102: 79.83,-39.29 v2(79.83,-39.78)
  L03_SIG1 w0.121: 79.83,-39.29 79.38,-38.84 79.38,-37.37 77.83,-35.83 74.27,-35.83 73.65,-35.21 73.65,-34.64 72.03,-33.02 v1(69.14,-33.02)
  BOTTOM w0.135: C118.1 70.62,-31.54 v1(69.14,-33.02) 68.33,-33.02 66.21,-35.14 61.87,-35.14 61.33,-35.68 61.33,-44.41 60.78,-44.96 60.78,-48.54 58.72,-50.6 v1(58.72,-51.28)
SOC_ADC0_AIN2: length 59.1
  TOP w0.102: 78.7,-37.97 78.7,-38.08 79.2,-38.57 79.2,-38.62 U18.F21
  TOP w0.135: R144.2 R145.1 46.39,-53.89 47.58,-52.7 52.55,-52.7 v1(53.85,-51.41) ; v1(67.87,-32.33) 68.53,-31.67 72.36,-31.67 73.19,-30.85 77.66,-30.85 78.7,-31.89 78.7,-37.97
  BOTTOM w0.135: C110.1 67.61,-31.63 67.87,-31.89 v1(67.87,-32.33) 66.31,-33.89 62.35,-33.89 59.94,-36.3 59.94,-37.39 59.51,-37.82 59.51,-47.92 56.83,-50.6 56.41,-50.6 55.28,-51.73 54.17,-51.73 v1(53.85,-51.41)
SOC_ADC0_AIN3: length 56.6
  TOP w0.102: 78.97,-37.97 78.97,-38 79.67,-38.7 79.67,-39.04 U18.F20
  TOP w0.135: 78.97,-37.97 78.97,-31.78 77.77,-30.58 72.83,-30.58 72,-31.4 68.11,-31.4 67.36,-32.16 v1(66.27,-32.16) ; v1(54.91,-51.28) 53.22,-52.97 50.05,-52.97 49.14,-53.89 R147.1 R146.2
  BOTTOM w0.135: C108.1 66.11,-31.99 v1(66.27,-32.16) 66.27,-32.23 64.88,-33.62 62.24,-33.62 58.22,-37.64 58.22,-47.98 v1(54.91,-51.28)
SOC_ADC0_AIN4: length 64.1
  TOP w0.102: U18.H20 80.08,-39 80.08,-38.37 79.68,-37.97
  TOP w0.135: C33.1 65.14,-33.62 64.26,-32.74 v1(64.26,-32.26) 64.26,-31.81 64.68,-31.39 67.31,-31.39 67.84,-30.87 71.67,-30.87 72.5,-30.04 77.99,-30.04 79.53,-31.57 79.53,-37.31 79.53,-37.82 79.68,-37.97 ; v1(56.44,-51.28) 55.99,-51.28 54.01,-53.26 52.51,-53.26 51.88,-53.89 R149.1 R148.2
  BOTTOM w0.135: v1(56.44,-51.28) 55.63,-52.1 52.76,-52.1 52.2,-51.54 52.2,-50.6 52.76,-50.04 52.76,-41.96 62.46,-32.26 v1(64.26,-32.26)
SOC_ADC0_AIN5: length 50.5
  TOP w0.102: 78.44,-37.97 78.44,-38.1 78.89,-38.56 U18.E21
  TOP w0.135: v1(57.45,-51.28) 57.45,-51.79 56.72,-52.53 55.99,-52.53 54.62,-53.89 R151.1 R150.2 ; 78.44,-37.97 78.44,-32 77.55,-31.11 73.41,-31.11 72.42,-32.11 v1(68.86,-32.11)
  BOTTOM w0.135: v1(57.45,-51.28) 60.5,-48.23 60.5,-44.58 61.06,-44.02 61.06,-35.57 62.46,-34.16 66.8,-34.16 v1(68.86,-32.11) 69.11,-31.85 C117.1
SOC_ADC0_AIN6: length 58.2
  TOP w0.102: U18.G20 79.88,-39.3 79.88,-38.58 79.27,-37.97
  TOP w0.135: v1(54.97,-50.22) 58.57,-50.22 60.3,-51.94 60.3,-53.66 R155.1 R154.2 ; C35.1 66.65,-33.62 66.18,-33.15 65.82,-33.15 v1(65.28,-32.61) 65.28,-32.17 65.77,-31.67 67.41,-31.67 67.95,-31.14 71.79,-31.14 72.61,-30.31 77.88,-30.31 79.24,-31.67 79.24,-37.94 79.27,-37.97
  BOTTOM w0.135: v1(65.28,-32.61) 64.54,-33.35 62.13,-33.35 55.68,-39.8 55.68,-49.5 v1(54.97,-50.22)
SOC_ADC0_AIN7: length 51.7
  TOP w0.102: U18.E20 78.58,-39 78.58,-38.53 78.16,-38.11 78.16,-37.97
  TOP w0.135: R156.2 R157.1 63.22,-53.49 63.22,-52.35 60.91,-50.04 v1(59.99,-50.04) ; 78.16,-37.97 78.16,-37.97 78.16,-32.11 77.44,-31.38 73.85,-31.38 72.67,-32.56 v1(70.43,-32.56) 69.37,-33.62 C36.1
  BOTTOM w0.135: v1(70.43,-32.56) 70.12,-32.88 69.94,-32.88 67.41,-35.41 61.98,-35.41 61.6,-35.79 61.6,-37.44 62.36,-38.2 62.36,-44.32 61.77,-44.91 61.77,-48.26 v1(59.99,-50.04)
SOC_CLKIN: length 5.6
  TOP w0.102: 77.8,-37.97 77.8,-38.04 78.38,-38.62 78.38,-39.3 U18.D20
  TOP w0.135: U11.4 77.42,-34.82 77.24,-35 77.24,-37.41 77.8,-37.97
SOC_CLKIN_BUFF: length 67.8
  TOP w0.135: v1(76.12,-33.65) U11.2 ; R46.2 v1(115.27,-27.3)
  L03_SIG1 w0.121: v1(115.27,-27.3) 114.46,-28.11 112.91,-28.11 110.69,-30.33 110.69,-31.19 109.58,-32.31 107.82,-32.31 105.07,-29.56 105.07,-29.43 104.68,-29.03 104.54,-29.03 104.4,-28.88 97.94,-28.88 96.69,-30.13 93.92,-30.13 93.57,-30.47 93.57,-31.03 93.12,-31.49 92.56,-31.49 91.87,-30.8 91.87,-30.71 91.54,-30.39 90.99,-30.39 90.14,-31.23 88.34,-31.23 88.01,-30.9 88.01,-30.37 87.28,-29.64 85.75,-29.64 83.59,-27.48 83.59,-26.91 82.04,-25.35 79.65,-25.35 79.15,-25.85 77.61,-25.85 77.34,-25.58 72.44,-25.58 71.76,-24.9 70.39,-24.9 70.14,-25.15 70.14,-26.03 76.12,-32.02 v1(76.12,-33.65)
SOC_CLKIN_BUFF_R: length 2.6
  TOP w0.135: R46.1 116.93,-26.72 117.16,-26.49 U6.3
SOC_CPSW_RGMII1_TXC: length 1.5
  TOP w0.102: U18.W13 85.93,-42.85 v2(85.93,-43.36)
  BOTTOM w0.135: v2(85.93,-43.36) 86.21,-43.64 R287.1
SOC_EMU0: length 58.5
  TOP w0.102: U18.C5 77.89,-47.26 v2(77.86,-47.29)
  TOP w0.135: v1(31.39,-42.47) 30.76,-42.47 29.69,-41.4 29.69,-40.44 28.79,-39.53 U16.5
  L03_SIG1 w0.121: v1(31.39,-42.47) 36.7,-42.47 37.25,-43.02 38.35,-43.02 39.15,-43.81 44.2,-43.81 44.99,-43.02 63.84,-43.02 65.18,-44.35 65.18,-45.4 65.92,-46.14 66.85,-46.14 69.42,-48.71 71.59,-48.71 73.37,-50.49 74.67,-50.49 v2(77.86,-47.29)
SOC_EMU1: length 66
  TOP w0.102: U18.B3 77.11,-47.54 76.77,-47.54
  TOP w0.114: 76.05,-48.99 76.34,-48.7 76.34,-47.96 76.77,-47.54
  TOP w0.135: v1(73.56,-55.02) 73.92,-54.66 73.92,-51.13 76.05,-48.99 ; U16.4 31.61,-39.53 v1(32,-39.14)
  L03_SIG1 w0.121: v1(73.56,-55.02) 73.56,-52.78 72.06,-51.28 72.06,-50.24 70.79,-48.97 69.27,-48.97 66.69,-46.4 65.81,-46.4 64.9,-45.49 64.9,-44.43 63.74,-43.27 45.24,-43.27 44.2,-44.32 39.15,-44.32 38.1,-43.27 37.13,-43.27 36.79,-42.94 31.2,-42.94 30.89,-42.62 30.89,-40.26 v1(32,-39.14)
SOC_I2C0_SCL: length 223.6
  TOP w0.135: R141.1 146.3,-54.1 v1(147.02,-54.81) ; U17.6 64.69,-38.84 65.48,-38.05 66.75,-38.05 v1(67.21,-38.51) 67.84,-39.14 R93.1
  L03_SIG1 w0.121: v1(38.05,-29.79) 39.04,-30.78 41.64,-30.78 42.07,-30.35 45.21,-30.35 45.87,-31.01 54.33,-31.01 57,-33.68 61.32,-33.68 62.79,-35.15 65.17,-35.15 67.21,-37.19 v1(67.21,-38.51) ; v1(156.82,-22.64) 153.75,-25.71 v1(153.75,-33.4) 153.75,-47.64 147.02,-54.37 v1(147.02,-54.81)
  BOTTOM w0.135: U35.15 v1(153.75,-33.4) ; R237.2 67.23,-38.48 v1(67.21,-38.51) ; v1(38.05,-29.79) 38.05,-28.98 37.52,-28.45 37.52,-26.82 40.44,-23.9 40.44,-21.59 38.66,-19.81 38.66,-15.04 40.06,-13.64 71.71,-13.64 74.35,-16.27 82.48,-16.27 83.61,-15.14 83.61,-14.35 86.06,-11.9 136.24,-11.9 146.98,-22.64 v1(156.82,-22.64)
SOC_I2C0_SCL_BP: length 27.7
  TOP w0.135: J5.17 125.78,-60 127.61,-60 130.49,-62.89 139.77,-62.89 139.9,-62.76 139.9,-61.65 143.43,-58.12 143.43,-55.28 144.57,-54.14 R141.2
SOC_I2C0_SCL_RC: length 9.2
  TOP w0.102: 76.05,-41.23 76.16,-41.23 76.23,-41.3 77.38,-41.3 U18.B16
  TOP w0.135: R93.2 C47.1 69.94,-40.55 70.18,-40.79 72.85,-40.79 73.29,-41.23 76.05,-41.23
SOC_I2C0_SDA: length 228
  TOP w0.135: R97.1 68.96,-42 67.49,-40.53 67.49,-39.62 66.37,-38.51 v1(65.91,-38.51) 65.6,-38.51 65.34,-38.76 U17.5 ; R158.1 v1(146.23,-55.6)
  L03_SIG1 w0.121: v1(158.8,-23.39) 156.13,-26.06 v1(156.13,-33.4) 156.13,-48.07 148.6,-55.6 v1(146.23,-55.6) ; v1(37.91,-30.82) 39.4,-32.31 55.04,-32.31 56.82,-34.09 61.27,-34.09 62.59,-35.41 65.06,-35.41 65.91,-36.26 v1(65.91,-38.51)
  BOTTOM w0.135: U35.2 v1(156.13,-33.4) ; v1(65.91,-38.51) R238.2 ; v1(158.8,-23.39) 147.35,-23.39 136.13,-12.17 86.18,-12.17 83.88,-14.46 83.88,-15.28 82.62,-16.54 74.19,-16.54 71.55,-13.91 40.3,-13.91 38.93,-15.28 38.93,-19.46 40.74,-21.27 40.74,-23.98 37.8,-26.92 37.8,-28.07 38.48,-28.75 38.48,-30.25 v1(37.91,-30.82)
SOC_I2C0_SDA_BP: length 24.8
  TOP w0.135: J5.19 129.63,-63.74 133.87,-63.74 133.9,-63.77 141.36,-63.77 143.16,-61.97 143.16,-59 144.52,-57.64 R158.2
SOC_I2C0_SDA_RC: length 9.9
  TOP w0.102: U18.B15 77.08,-41.5 76.05,-41.5
  TOP w0.135: 76.05,-41.5 73.17,-41.5 72.79,-41.12 71.88,-41.12 70.69,-42.32 70.22,-42.32 R97.2 69.94,-41.35 70.03,-41.26 v1(70.03,-41.26)
  BOTTOM w0.135: C161.1 70.04,-41.24 70.03,-41.25 v1(70.03,-41.26)
SOC_I2C1_SCL: length 135.5
  TOP w0.102: 76.05,-40.64 76.07,-40.62 76.7,-40.62 U18.A17
  TOP w0.135: 76.05,-40.64 73.63,-40.64 72.91,-39.92 72.1,-39.92 72.09,-39.9 72.06,-39.9 70.08,-37.92 69.9,-37.92 v1(69.55,-37.57) R88.2 ; v1(42.72,-39.09) 41.81,-40 41.81,-52.55 39.17,-55.19 39.17,-62.51 39.89,-63.23 59.05,-63.23 J1.17 ; v1(7.42,-29.51) 8.08,-30.17 U9.2
  L03_SIG1 w0.121: v1(7.42,-29.51) 10.52,-32.61 18.82,-32.61 19.13,-32.3 26.41,-32.3 27.53,-33.42 31.15,-33.42 32.55,-32.01 36.58,-32.01 39.65,-35.08 39.65,-36.7 42.04,-39.09 v1(42.72,-39.09) 43.33,-38.48 54.66,-38.48 55.45,-39.27 55.45,-39.93 56.03,-40.51 56.87,-40.51 57.33,-40.06 57.33,-37.27 58.1,-36.5 61.19,-36.5 62.03,-37.34 62.88,-37.34 64.83,-39.29 69.01,-39.29 69.55,-38.76 v1(69.55,-37.57)
SOC_I2C1_SDA: length 138.9
  TOP w0.102: U18.B18 77.11,-40.04 76.05,-40.04
  TOP w0.135: J1.19 61.32,-63.5 39.78,-63.5 38.86,-62.59 38.86,-54.99 41.38,-52.48 41.38,-39.55 v1(42.77,-38.15) ; R82.2 v1(69.6,-36.17) 70,-36.58 70,-36.9 70.33,-37.23 70.33,-37.41 72.29,-39.37 75.11,-39.37 75.77,-40.04 76.05,-40.04 ; U9.3 8.34,-29.52 v1(8.34,-29.51)
  L03_SIG1 w0.121: v1(8.34,-29.51) 9.99,-31.17 11.94,-31.17 13.11,-32.33 18.64,-32.33 18.93,-32.05 26.52,-32.05 27.63,-33.16 30.87,-33.16 32.28,-31.76 36.68,-31.76 40.06,-35.13 40.06,-36.45 41.76,-38.15 v1(42.77,-38.15) 54.76,-38.15 55.73,-39.12 55.73,-39.85 56.05,-40.17 56.78,-40.17 56.97,-39.98 56.97,-37.26 57.99,-36.24 61.39,-36.24 62.23,-37.09 62.98,-37.09 64.91,-39.01 68.78,-39.01 69.09,-38.71 69.09,-36.68 v1(69.6,-36.17)
SOC_I2C1_TA_SCL: length 15.2
  TOP w0.135: v1(9.3,-22.5) 9.33,-22.54 9.33,-25.99 9.33,-27.12 8.17,-28.28 8,-28.28 6.11,-30.17 U9.7
  BOTTOM w0.135: J15.36 9.01,-22.22 v1(9.3,-22.5) R187.2
SOC_I2C1_TA_SDA: length 17
  TOP w0.135: U9.6 6.11,-29.52 7.69,-27.94 8.03,-27.94 9.06,-26.91 9.06,-26.46 9.06,-26.46 9.06,-23.72 8.76,-23.42 8.76,-21.31 v1(9.45,-20.62)
  BOTTOM w0.135: R182.2 v1(9.45,-20.62) 8.15,-20.62 7.56,-21.22 J15.38
SOC_PRG1_RGMII1_TXC: length 4.6
  TOP w0.102: v2(85.93,-45.86) 85.93,-46.28 U18.W6
  BOTTOM w0.135: R286.1 87.43,-47.8 85.93,-46.3 v2(85.93,-45.86)
SOC_RESET_REQZ: length 22.6
  TOP w0.102: v2(77.86,-40.35) 77.89,-40.39 U18.C17
  TOP w0.135: TP24.1 59.44,-38.3 v1(59.44,-37.29) 59.26,-37.11 U13.2
  L03_SIG1 w0.121: v1(59.44,-37.29) 59.75,-37.6 62.77,-37.6 64.78,-39.61 71.07,-39.61 71.09,-39.63 77.14,-39.63 v2(77.86,-40.35)
SOC_RESETSTATZ: length 15.9
  TOP w0.102: U18.E19 78.47,-39.82 v2(78.44,-39.78)
  TOP w0.135: v1(71.96,-35.38) 71.96,-34.93 71.7,-34.67 TP13.1
  L03_SIG1 w0.121: v2(78.44,-39.78) 77,-38.34 74.19,-38.34 73.91,-38.63 71.09,-38.63 70.37,-37.91 70.37,-37.06 70.62,-36.8 71.53,-36.8 71.96,-36.37 v1(71.96,-35.38)
  BOTTOM w0.135: v1(71.96,-35.38) 71.7,-35.38 71.14,-34.82 R234.2
SOC_TCK: length 27.6
  TOP w0.102: U18.C6 77.89,-45.89 v2(77.86,-45.86)
  TOP w0.135: v1(70.08,-47.52) 69.29,-47.52 67.13,-49.68 67.13,-50.27 67.32,-50.46 67.32,-56.48 67.12,-56.68 67.12,-59.81 67.51,-60.2 69.79,-60.2 70.31,-59.68 R162.1
  L03_SIG1 w0.121: v2(77.86,-45.86) 77.18,-45.86 75.03,-48.01 73.05,-48.01 71.85,-46.8 70.8,-46.8 v1(70.08,-47.52)
SOC_TDI: length 17.1
  TOP w0.102: U18.A3 76.55,-48.16 76.55,-48.93 76.05,-49.43
  TOP w0.135: U25.5 70.69,-58.52 71.57,-59.4 72.93,-59.4 74.19,-58.14 74.19,-51.29 76.05,-49.43
SOC_TDO: length 1.8
  BOTTOM w0.135: U42.2 68.49,-54.11 69.13,-54.74 R271.1
SOC_TMS: length 17.1
  TOP w0.114: U18.B4 76.68,-47.31 76.1,-47.9
  TOP w0.135: U25.6 71.34,-58.54 71.93,-59.13 72.82,-59.13 73.1,-58.85 73.1,-54.66 73.65,-54.11 73.65,-51.01 76.1,-48.57 76.1,-47.9
SOC_TRST#: length 22
  TOP w0.102: U18.B6 77.11,-46.04 76.67,-46.04 76.3,-46.41 76.08,-46.41 76.05,-46.43
  TOP w0.135: 76.05,-46.43 75.23,-46.43 73.91,-47.76 72.96,-47.76 R120.2 72.71,-48.43 72.47,-48.67 68.58,-48.67 67.42,-49.82 67.42,-50.18 67.59,-50.35 67.59,-52.86 69.34,-54.61 70.61,-54.61 71.99,-55.99 U25.7
SPDT_MCAN/EQEP_MUX_SEL: length 44.5
  TOP w0.135: U22.1 R128.2 150.96,-49.29 v1(151.21,-49.05)
  L03_SIG1 w0.121: v1(121.16,-51.56) 131.65,-51.56 132.11,-52.02 132.73,-52.02 133.44,-51.31 136.06,-51.31 137.01,-50.35 v1(138.43,-50.35) ; v1(140.91,-52.52) 141.73,-51.71 142.98,-51.71 143.23,-51.97 144.26,-51.97 145.13,-52.83 145.57,-52.83 145.85,-52.55 147.04,-52.55 147.16,-52.68 148.34,-52.68 151.21,-49.81 v1(151.21,-49.05)
  BOTTOM w0.135: v1(138.43,-50.35) 138.84,-50.76 138.84,-51.88 138.97,-52.02 139.88,-52.02 140.13,-51.77 140.13,-50.45 140.46,-50.11 140.77,-50.11 141.23,-50.58 141.23,-52.21 v1(140.91,-52.52) ; v1(121.16,-51.56) 120.71,-51.56 120.4,-51.87 U52.10
SPI0_CLK: length 74
  TOP w0.102: 76.05,-45.82 76.31,-45.82 76.52,-45.61 77.1,-45.61 U18.B8
  TOP w0.135: 76.05,-45.82 74.99,-45.82 74.19,-46.61 71.28,-46.61 71.19,-46.7 69.36,-46.7 69.34,-46.71 66.5,-49.56 v1(66.5,-51.61)
  L03_SIG1 w0.121: J5.13 117.43,-63.27 99.64,-63.27 97.9,-61.53 91.71,-61.53 89.34,-59.17 89.14,-59.13 74.4,-59.13 70.31,-55.04 70.3,-55.04 68.85,-53.58 68.83,-53.55 68.83,-52.43 68.02,-51.61 v1(66.5,-51.61)
SPI0_CS1: length 169
  TOP w0.102: U18.B7 76.61,-45.81 76.32,-46.1 76.07,-46.1 76.05,-46.08
  TOP w0.135: v1(127.86,-65.1) 127.55,-65.42 120.36,-65.42 120.03,-65.09 100.85,-65.09 99.24,-63.47 96.24,-63.47 95.87,-63.11 85.97,-63.11 82.49,-59.63 78.85,-59.63 78.01,-60.47 67.4,-60.47 66.85,-59.92 66.85,-56.57 67.05,-56.37 67.05,-50.77 66.85,-50.57 66.85,-49.58 69.47,-46.97 72.7,-46.97 73.22,-47.49 73.8,-47.49 75.2,-46.08 76.05,-46.08
  L03_SIG1 w0.121: v1(114.84,-55.46) 115.61,-55.46 116.29,-56.14 125.06,-56.14 125.75,-55.45 v1(127.89,-55.45)
  BOTTOM w0.135: v1(127.89,-55.45) 128.21,-55.77 128.21,-55.79 128.29,-55.87 128.29,-58.15 128.32,-58.17 128.32,-61.72 128.29,-61.74 128.29,-64.67 v1(127.86,-65.1) ; J6.6 107.67,-13.84 103.84,-13.84 102.94,-14.73 102.94,-19.91 103.95,-20.92 103.96,-20.93 103.98,-20.93 105.26,-22.2 109.85,-22.2 109.99,-22.34 109.99,-24.18 109.5,-24.67 109.5,-25.3 110.58,-26.38 110.58,-30.34 110.58,-30.37 110.58,-31.63 111.09,-32.14 111.09,-34.43 113.74,-37.08 113.74,-50.65 113.11,-51.28 113.11,-55.7 113.28,-55.88 114.43,-55.88 v1(114.84,-55.46)
SPI0_D0: length 104
  TOP w0.102: 76.05,-45.55 76.29,-45.55 76.52,-45.31 U18.A8
  TOP w0.135: 76.05,-45.55 74.88,-45.55 74.08,-46.34 71.16,-46.34 71.08,-46.43 69.24,-46.43 69.19,-46.48 68.83,-46.84 v1(66.45,-46.84)
  BOTTOM w0.135: J6.12 114.7,-13.24 86.62,-13.24 84.96,-14.91 84.96,-15.75 83.04,-17.66 82.6,-17.66 66.66,-17.66 63.38,-20.95 63.38,-24.06 68.3,-28.98 71.53,-28.98 72.54,-30 72.54,-31.47 69.88,-34.13 69.88,-34.64 69.04,-35.48 69.04,-38.61 65.66,-41.98 65.66,-46.05 v1(66.45,-46.84)
SPI0_D1: length 104.2
  TOP w0.102: U18.C9 77.89,-44.39 v2(77.86,-44.36)
  TOP w0.135: J6.14 117.4,-13.41 85.5,-13.41 81.91,-16.99 76.81,-16.99 74.98,-15.16 69.72,-15.16 67.88,-17.01 67.88,-29.74 66.78,-30.84 63.49,-30.84 62.81,-31.52 62.81,-36.41 62.41,-36.82 62.41,-39.34 v1(61.93,-39.83)
  L03_SIG1 w0.121: v1(61.93,-39.83) 62.89,-39.83 64.34,-41.27 66.49,-41.27 67.18,-41.97 67.18,-45.03 68.26,-46.11 75.32,-46.11 77.08,-44.36 v2(77.86,-44.36)
SPI3_CLK: length 44.5
  TOP w0.102: U18.N3 83.32,-47.81 v2(83.37,-47.86)
  L03_SIG1 w0.121: v2(83.37,-47.86) 83.37,-49.2 86.68,-52.51 86.68,-54.89 v1(87.18,-55.4)
  BOTTOM w0.135: J1.13 57.5,-62.72 65.93,-62.72 67.39,-61.26 76.19,-61.26 78.4,-59.06 83.1,-59.06 86.44,-55.72 86.86,-55.72 v1(87.18,-55.4)
SPI3_CS0: length 87.5
  TOP w0.102: U18.E1 78.63,-49.08 78.63,-49.66
  TOP w0.135: 78.63,-49.66 78.63,-49.69 78.29,-50.03 78.22,-50.03 77.05,-51.2 76.8,-51.2 76.17,-51.82 v1(76.17,-58.46)
  BOTTOM w0.135: v1(76.17,-58.46) 74.18,-60.46 67.21,-60.46 66.65,-59.89 66.65,-59.56 65.93,-58.84 65.88,-58.84 63.98,-56.94 58.65,-56.94 58.49,-57.11 53.59,-57.11 50.02,-57.11 50.01,-57.11 49.98,-57.1 49.97,-57.1 44.22,-51.36 44.22,-50.99 44.22,-40.95 46.23,-38.94 46.23,-37.64 47.37,-36.5 47.37,-34.39 48.29,-33.47 48.29,-29.86 48.32,-29.82 48.32,-24.93 44.55,-21.16 44.55,-16.77 J2.6
SPI3_CS1: length 51.8
  TOP w0.102: U18.N4 83.35,-47.31 v2(83.37,-47.29)
  TOP w0.135: v1(92.22,-56.13) 96.98,-56.13 97.36,-55.75 102.01,-55.75 102.84,-54.91 105.66,-54.91 105.87,-54.71 115.8,-54.71 116.31,-55.22 117.2,-55.22 117.47,-54.94 119.8,-54.94 119.94,-54.81 119.94,-53.24 v1(120.7,-52.48)
  L03_SIG1 w0.121: v1(92.22,-56.13) 91.91,-55.82 87.01,-55.82 84.1,-52.92 84.1,-50.39 82.85,-49.15 82.85,-47.81 v2(83.37,-47.29)
  BOTTOM w0.135: U50.3 v1(92.22,-56.13) ; v1(120.7,-52.48) 120.49,-52.27 U52.11
SPI3_CS1/PRG0_PRU1_GPI11: length 95.6
  BOTTOM w0.135: J2.18 59.74,-16.82 59.74,-20.63 55.02,-25.35 55.02,-26.01 54.16,-26.87 54.16,-33.9 49.81,-38.25 49.33,-38.25 47.4,-40.18 47.4,-51.13 49.71,-53.44 52.45,-53.44 53.58,-54.57 62.27,-54.57 62.88,-55.19 64.51,-55.19 66.55,-57.23 73.33,-57.23 74.28,-56.27 80.02,-56.27 80.48,-55.81 81.01,-55.81 81.2,-56.01 81.57,-56.01 82.66,-54.92 86.03,-54.92 86.52,-54.43 87.58,-54.43 88.22,-55.07 93.09,-55.07 93.22,-55.2 U50.5
SPI3_D0: length 16.8
  TOP w0.102: U18.N1 83.17,-49.09 83.17,-49.66
  TOP w0.135: 83.17,-49.66 83.17,-50.15 83.69,-50.67 83.69,-52.66 86.23,-55.2 86.23,-55.92 86.09,-56.06 86.09,-56.35 86,-56.44 v1(86,-56.88)
  BOTTOM w0.135: v1(86,-56.88) 86.55,-56.34 89,-56.34 89.63,-56.96 89.63,-58.69 90.18,-59.24 U50.16
SPI3_D0/GPIO1_18: length 95.5
  BOTTOM w0.135: U50.2 91.82,-56.34 91.79,-56.31 91.79,-55.98 91.15,-55.34 88.11,-55.34 87.47,-54.7 86.7,-54.7 85.21,-56.18 82.26,-56.18 81.99,-56.45 81.99,-56.74 81.64,-57.09 78.29,-57.09 77.71,-57.67 75.73,-57.67 73.48,-59.92 67.44,-59.92 67.18,-59.67 67.18,-59.34 66.15,-58.3 66.1,-58.3 64.2,-56.4 58.23,-56.4 58.06,-56.57 51.31,-56.57 44.91,-50.16 44.91,-41.07 48.08,-37.9 48.08,-37.54 48.89,-36.73 48.89,-33.05 48.82,-32.98 48.82,-30.08 48.87,-30.04 48.87,-24.05 52.12,-20.81 52.12,-17.53 52.04,-17.46 52.04,-16.9 J2.12
SPI3_D1: length 91.9
  TOP w0.102: U18.N2 82.61,-48.59 82.61,-49.09 82.9,-49.37 82.9,-49.66
  TOP w0.135: v1(85.26,-55.35) 83.41,-53.5 83.41,-50.77 82.9,-50.26 82.9,-49.66
  BOTTOM w0.135: J2.14 54.71,-16.77 54.71,-19.96 50.01,-24.66 50.01,-35.99 48.5,-37.51 48.5,-37.86 45.21,-41.15 45.21,-50.09 51.43,-56.3 52.78,-56.3 57.95,-56.3 58.12,-56.13 64.31,-56.13 66.21,-58.03 66.31,-58.03 66.36,-58.09 73.71,-58.09 74.4,-57.4 77.6,-57.4 78.18,-56.82 81.24,-56.82 82.71,-55.35 v1(85.26,-55.35)
SYNC1_OUT: length 111.3
  TOP w0.102: 76.05,-40.32 U18.A18
  TOP w0.135: J5.3 105.66,-62.34 105.66,-63.02 105.42,-63.26 101.36,-63.26 98.2,-60.1 95.39,-60.1 95.37,-60.07 v1(94.92,-60.07) ; v1(67.67,-63.88) 67.67,-63.43 65.18,-60.94 65.18,-56.64 64.52,-55.98 64.52,-52.65 60.59,-48.73 60.59,-43.96 62.71,-41.83 62.71,-36.93 64.21,-35.43 65.3,-35.43 66.83,-36.96 69.65,-36.96 70.05,-37.36 70.05,-37.52 72.19,-39.65 75.01,-39.65 75.67,-40.32 76.05,-40.32
  BOTTOM w0.135: v1(67.67,-63.88) 70.15,-63.88 71.25,-64.99 71.27,-65 71.28,-65.01 71.29,-65.01 71.31,-65.01 74.43,-65.01 77.08,-62.36 77.1,-62.34 79.03,-60.41 83.5,-60.41 86.53,-63.44 89.46,-63.44 91.8,-65.79 105.23,-65.79 106.79,-64.23 J5.3 ; v1(94.92,-60.07) 94.54,-60.44 U50.8
SYNC2_OUT: length 107.9
  TOP w0.135: R140.2 149.98,-52.96 144.42,-58.52 v1(144.42,-65.48)
  L03_SIG1 w0.121: J1.18 62.36,-59.97 62.36,-62.41 63.25,-63.3 70.15,-63.3 73.3,-60.15 87.12,-60.15 92.76,-65.79 118.87,-65.79 120.88,-63.78 137.72,-63.78 139.42,-65.48 v1(144.42,-65.48)
SYNC3_OUT: length 118.9
  TOP w0.135: v1(159.77,-64.26) 159.77,-55.19 160.87,-54.09 R131.2
  L03_SIG1 w0.121: v1(159.77,-64.26) 157.91,-66.12 146.48,-66.12 145.42,-65.05 139.42,-65.05 137.95,-63.58 137.88,-63.58 137.82,-63.52 120.77,-63.52 118.76,-65.54 92.86,-65.54 87.22,-59.9 72.82,-59.9 69.8,-62.92 65.84,-62.92 65.18,-62.26 65.18,-60.24 J1.20
SYS_BOOTMODE3: length 33.2
  TOP w0.135: v1(27.66,-22.99) 27.97,-23.3 27.97,-23.36 28.14,-23.52 U4.3 ; R16.1 v1(13.84,-22.86) 14.35,-23.37 SW4.1
  L03_SIG1 w0.121: v1(27.66,-22.99) 22.3,-22.99 22.17,-22.86 v1(13.84,-22.86)
  BOTTOM w0.135: U26.2 25.57,-17.84 26.06,-17.35 28.96,-17.35 29.87,-18.26 29.87,-23.57 28.96,-24.49 28.17,-24.49 27.66,-23.97 v1(27.66,-22.99)
SYS_BOOTMODE4: length 28.3
  TOP w0.135: R27.1 v1(13.84,-24.36) 14.12,-24.64 SW4.2 ; U4.4 v1(28.57,-24.02)
  L03_SIG1 w0.121: v1(13.84,-24.36) 26.24,-24.36 26.57,-24.02 v1(28.57,-24.02)
  BOTTOM w0.135: U26.3 26.07,-17.97 26.38,-17.67 26.39,-17.67 26.42,-17.64 28.08,-17.64 29.51,-19.08 29.51,-23.08 v1(28.57,-24.02)
SYS_BOOTMODE5: length 33.3
  TOP w0.135: U4.5 27.82,-24.52 27,-23.7 27,-22.88 27.96,-21.92 v1(29.08,-21.92) ; SW4.3 15.42,-25.86 v1(13.84,-25.86) R33.1
  L03_SIG1 w0.121: v1(13.84,-25.86) 14.93,-24.77 26.21,-24.77 26.63,-24.34 27.85,-24.34 28.09,-24.59 28.78,-24.59 29.08,-24.28 v1(29.08,-21.92)
  BOTTOM w0.135: U26.4 26.57,-18.03 26.7,-17.91 27.8,-17.91 29.08,-19.19 v1(29.08,-21.92)
SYS_BOOTMODE6: length 27.5
  TOP w0.135: U4.6 v1(28.57,-25.02) ; SW4.4 14.02,-27.18 v1(13.84,-27.36) R47.1
  L03_SIG1 w0.121: v1(13.84,-27.36) 15.19,-27.36 17.45,-25.09 22.48,-25.09 22.52,-25.1 26.29,-25.1 26.78,-24.61 27.58,-24.61 27.99,-25.02 v1(28.57,-25.02)
  BOTTOM w0.135: v1(28.57,-25.02) 28.12,-25.02 27.22,-24.13 27.22,-22.81 28.73,-21.31 28.73,-19.75 28.39,-19.42 U26.5
SYS_BOOTMODE7: length 26.2
  TOP w0.135: R52.1 v1(13.84,-28.85) 14.25,-28.45 SW4.5 ; 29.37,-25.52 27.82,-25.52 v1(27.33,-25.03)
  L03_SIG1 w0.121: v1(13.84,-28.85) 14.28,-28.85 17.56,-25.58 26.29,-25.58 26.83,-25.03 v1(27.33,-25.03)
  BOTTOM w0.135: U26.7 28.19,-20.42 28.45,-20.68 28.45,-21.2 26.92,-22.73 26.92,-24.62 v1(27.33,-25.03)
SYS_BOOTMODE8: length 27.5
  TOP w0.135: R66.1 v1(13.84,-30.35) 14.48,-29.72 SW4.6 ; v1(27.46,-26.57) 28,-26.02 U4.8
  L03_SIG1 w0.121: v1(27.46,-26.57) 25.76,-28.27 17.75,-28.27 15.67,-30.35 v1(13.84,-30.35)
  BOTTOM w0.135: U26.8 27.75,-20.92 27.89,-21.06 27.89,-21.38 25.96,-23.31 25.96,-24.51 27.46,-26.01 v1(27.46,-26.57)
SYS_BOOTMODE9: length 27.3
  TOP w0.135: U4.9 28.16,-26.52 v1(27.23,-27.46) ; SW4.7 14.71,-30.99 v1(13.84,-31.85) R69.1
  L03_SIG1 w0.121: v1(27.23,-27.46) 26.14,-28.55 17.93,-28.55 14.63,-31.85 v1(13.84,-31.85)
  BOTTOM w0.135: v1(27.23,-27.46) 26.9,-27.13 26.9,-25.96 25.65,-24.71 25.65,-23.23 26.57,-22.31 U26.9
TA_BOOTMODE_I2C_SCL: length 27.9
  TOP w0.135: v1(8.02,-21.56) 7.59,-21.13 7.59,-18.8 11.61,-14.78 15.47,-14.78 19.14,-18.45 21.69,-18.45 24.31,-21.07 v1(24.31,-21.51)
  BOTTOM w0.135: U26.12 24.41,-21.62 v1(24.31,-21.51) ; R186.2 v1(8.02,-21.56) 7.87,-21.72 J15.37
TA_BOOTMODE_I2C_SDA: length 24.6
  TOP w0.135: v1(8.02,-19.68) 8.02,-18.75 11.72,-15.05 15.36,-15.05 19.02,-18.72 21.26,-18.72 v1(23.55,-21.01)
  BOTTOM w0.135: v1(23.55,-21.01) 23.63,-20.92 U26.13 ; R178.2 v1(8.02,-19.68) 8.02,-20.15 7.45,-20.72 J15.39
TA_GPIO2: length 3.9
  TOP w0.135: v1(8.02,-25.32) 7.46,-25.88 TP6.1
  BOTTOM w0.135: J15.31 7.42,-24.72 v1(8.02,-25.32) R197.1
TA_GPIO3: length 43
  L03_SIG1 w0.121: v1(9.78,-24.38) 10.4,-24.38 11.48,-23.3 11.48,-21.13 15.62,-17 25.38,-17 25.94,-17.56 31.06,-17.56 31.72,-16.89 35.81,-16.89 36.43,-17.51 TP3.1
  BOTTOM w0.135: R196.1 v1(9.78,-24.38) 9.33,-24.38 9.17,-24.22 J15.32 ; U28.1 36.97,-22.29 36.43,-21.75 TP3.1
TA_GPIO4: length 30.2
  TOP w0.135: v1(8.02,-23.44) 6.58,-22 6.58,-19.43 11.5,-14.51 15.58,-14.51 16.66,-15.6 21.67,-15.6 23.5,-17.42 v1(24.77,-17.42)
  BOTTOM w0.135: J15.33 7.3,-23.72 7.58,-23.44 v1(8.02,-23.44) R189.1 ; U26.1 25.07,-17.73 v1(24.77,-17.42)
TA_PORZN: length 22.2
  TOP w0.135: v1(13.98,-15.64) 11.57,-15.64 10.72,-16.48 10.72,-18.82 11.35,-19.45 11.35,-27.2 v1(10.4,-28.14)
  BOTTOM w0.135: R211.1 v1(10.4,-28.14) 8.29,-28.14 6.87,-26.72 J15.27 ; Q8.3 v1(13.98,-15.64)
TA_POWERDOWN: length 44.7
  TOP w0.135: v1(8.05,-35.64) 16.31,-35.64 16.92,-36.25 16.92,-37.24 17.64,-37.96 37.8,-37.96 39.63,-36.13 R84.1
  BOTTOM w0.135: J15.26 6.87,-27.22 7.87,-28.23 7.87,-35.46 v1(8.05,-35.64)
TA_PWR_EN: length 3.4
  BOTTOM w0.508: U41.3 3.36,-45.15 R251.2
TA_SOC_INTN: length 122.1
  L03_SIG1 w0.121: v1(66.32,-66.24) 65.02,-64.95 39.09,-64.95 38.05,-65.99 31.59,-65.99 31.04,-65.44 31.04,-60.55 22.73,-52.25 22.73,-48.92 22.23,-48.41 16.1,-48.41 13.39,-51.13 13.39,-52.17 12.01,-53.54 12.01,-54.74 10.64,-56.11 7.39,-56.11 6.38,-55.09 6.38,-52.04 7.44,-50.98 7.44,-50.6 8.33,-49.71 8.33,-48.44 7.87,-47.98 5.49,-47.98 2.46,-44.96 2.46,-28.93 5.15,-26.25 v1(8.63,-26.25)
  BOTTOM w0.135: R202.1 8.65,-26.26 v1(8.63,-26.25) 7.99,-26.25 6.96,-25.22 J15.30 ; v1(66.32,-66.24) 66.12,-66.05 Q16.3
TA_WARMRESETN: length 33.5
  TOP w0.135: v1(24.18,-15.19) 23.86,-14.87 21.81,-14.87 21.41,-15.27 16.72,-15.27 15.69,-14.25 11.26,-14.25 6.2,-19.3 6.2,-26.06 7.34,-27.2 v1(8.02,-27.2)
  BOTTOM w0.135: R209.1 v1(8.02,-27.2) 7.04,-26.22 J15.28 ; v1(24.18,-15.19) 24.29,-15.3 Q7.3
TCA6408_EXP_ADDR: length 2.1
  BOTTOM w0.135: U26.16 R177.2
TCA6408_EXP_INT: length 2.2
  BOTTOM w0.135: U26.11 25.57,-22.35 24.94,-22.99 R191.1
TEST_LED1_GREEN: length 141.6
  TOP w0.102: U18.U19 85.32,-39.82 v2(85.35,-39.78)
  L03_SIG1 w0.121: v2(85.35,-39.78) 85.35,-39.06 87.93,-36.48 87.93,-35.62 88.37,-35.18 v1(88.87,-35.18) ; v1(103.07,-28.32) 104.24,-28.32 104.69,-28.77 104.78,-28.77 105.33,-29.32 105.33,-29.41 107.06,-31.14 110.08,-31.14 110.24,-30.99 110.24,-29.77 114.76,-25.25 115.56,-25.25 116.77,-24.04 v1(116.77,-23.6) ; v1(100.61,-18.36) 100.61,-16.97 104.6,-12.98 164.72,-12.98 167.08,-15.34 171.78,-15.34 v1(172.27,-14.85)
  BOTTOM w0.135: v1(172.27,-14.85) R173.2 Q6.3 ; v1(116.77,-23.6) 116.77,-23.62 116.63,-23.62 116.63,-23.59 U51.8 ; R216.1 88.61,-29.83 89.31,-30.52 89.31,-32.49 88.56,-33.24 88.56,-34.86 v1(88.87,-35.18) 89.79,-35.18 91.37,-36.76 93.26,-36.76 95.86,-34.16 97.16,-34.16 97.59,-33.73 97.59,-32.66 98.09,-32.16 98.57,-32.16 98.93,-31.8 98.93,-31.09 99.49,-30.53 100.86,-30.53 v1(103.07,-28.32) 102.62,-28.32 101.77,-27.47 101.77,-25.7 100.53,-24.46 100.53,-18.89 100.61,-18.81 v1(100.61,-18.36)
TEST_LED2_RED: length 157
  TOP w0.102: 76.05,-45.28 76.27,-45.28 76.44,-45.11 76.6,-45.11 U18.A9
  TOP w0.135: v1(66.09,-45.72) 66.73,-46.35 68.94,-46.35 69.12,-46.17 69.13,-46.16 70.97,-46.16 71.05,-46.07 73.87,-46.07 74.66,-45.28 76.05,-45.28
  L03_SIG1 w0.121: v1(167.52,-14.85) 165.4,-12.73 104.04,-12.73 v1(101.98,-14.78)
  BOTTOM w0.135: v1(167.52,-14.85) R172.2 Q5.3 ; v1(66.09,-45.72) 66.09,-41.94 70.05,-37.97 70.05,-36.88 70.15,-36.78 70.15,-34.24 72.87,-31.52 72.87,-29.95 71.64,-28.71 68.41,-28.71 63.65,-23.95 63.65,-21.06 66.78,-17.93 82.49,-17.93 83.15,-17.93 84.69,-16.4 85.23,-15.86 85.23,-15.02 86.73,-13.51 100.71,-13.51 v1(101.98,-14.78)
TEST_LED3_RED: length 175.2
  TOP w0.102: 78.18,-49.66 78.39,-49.44 U18.D1
  TOP w0.135: 78.18,-49.66 76.92,-50.92 76.69,-50.92 75.9,-51.71 75.9,-57.51 75.69,-57.71 75.69,-58.92 75.83,-59.05 77.88,-59.05 78.41,-58.52 80.16,-58.52 80.19,-58.55 82.93,-58.55 86.42,-62.03 98.61,-62.03 100.91,-64.33 101.12,-64.33 101.27,-64.49 117.12,-64.49 117.26,-64.35 121.19,-64.35 121.32,-64.48 v1(121.77,-64.48) 124.98,-64.48 125.53,-63.93 129.44,-63.93 129.55,-64.04 133.9,-64.04 134.27,-64.41 142.11,-64.41 143.87,-66.17 154.18,-66.17 154.53,-65.82 158.45,-65.82 158.47,-65.81 158.48,-65.81 158.48,-65.81 v1(160.38,-65.81)
  L03_SIG1 w0.121: v1(160.38,-65.81) 160.38,-55.3 159.48,-54.4 159.48,-52.86 158.04,-51.42 158.04,-28.36 168.31,-18.09 170.91,-18.09 v1(171.96,-17.04)
  BOTTOM w0.135: U52.1 117.69,-52.67 116.76,-53.6 116.76,-54.76 117.8,-55.79 118.65,-55.79 120.73,-57.86 120.73,-63.44 v1(121.77,-64.48) ; Q9.3 174.92,-17.1 R174.2 172.02,-17.1 v1(171.96,-17.04)
